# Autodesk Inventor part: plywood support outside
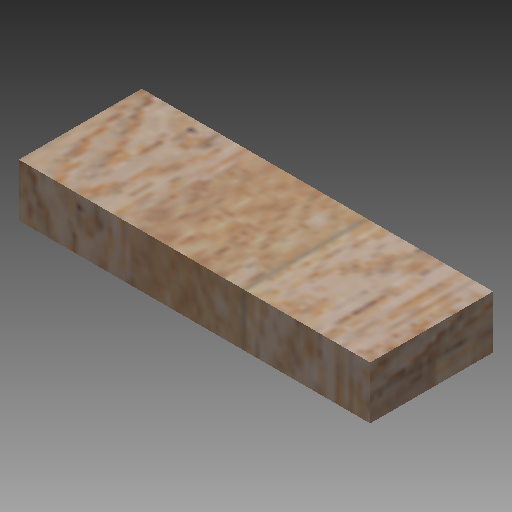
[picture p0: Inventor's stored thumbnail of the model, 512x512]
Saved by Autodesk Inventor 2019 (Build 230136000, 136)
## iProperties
Created: 2013-08
Part Number: plywood support outside
Material: Generic
Document SubType Name: Modeling
Designer: Patrick Rice
Density: 1 g/cm^3
Appearance: Red Oak - Natural
Author: Patrick Rice
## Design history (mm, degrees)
sketch "Sketch1"
  geometry: L1 (19.05, -44.45)-(-19.05, -44.45); L2 (-19.05, -44.45)-(-19.05, 44.45); L3 (-19.05, 44.45)-(19.05, 44.45); L4 (19.05, 44.45)-(19.05, -44.45); L5 (19.05, -44.45)-(-19.05, 44.45); L6 (-19.05, -44.45)-(19.05, 44.45); 1 further point
  constraints: 12 end point, 2 midpoint, 2 parallel, 1 horizontal, 1 perpendicular
  dimensions: "d0" = 38.1 distance of L2.end L3.end; "d1" = 88.9 distance of L1.end L2.end
extrude "Extrusion1" new body sketch "Sketch1" distance "d2" = 254; taper "d3" = 0 deg
body "Solid1"
